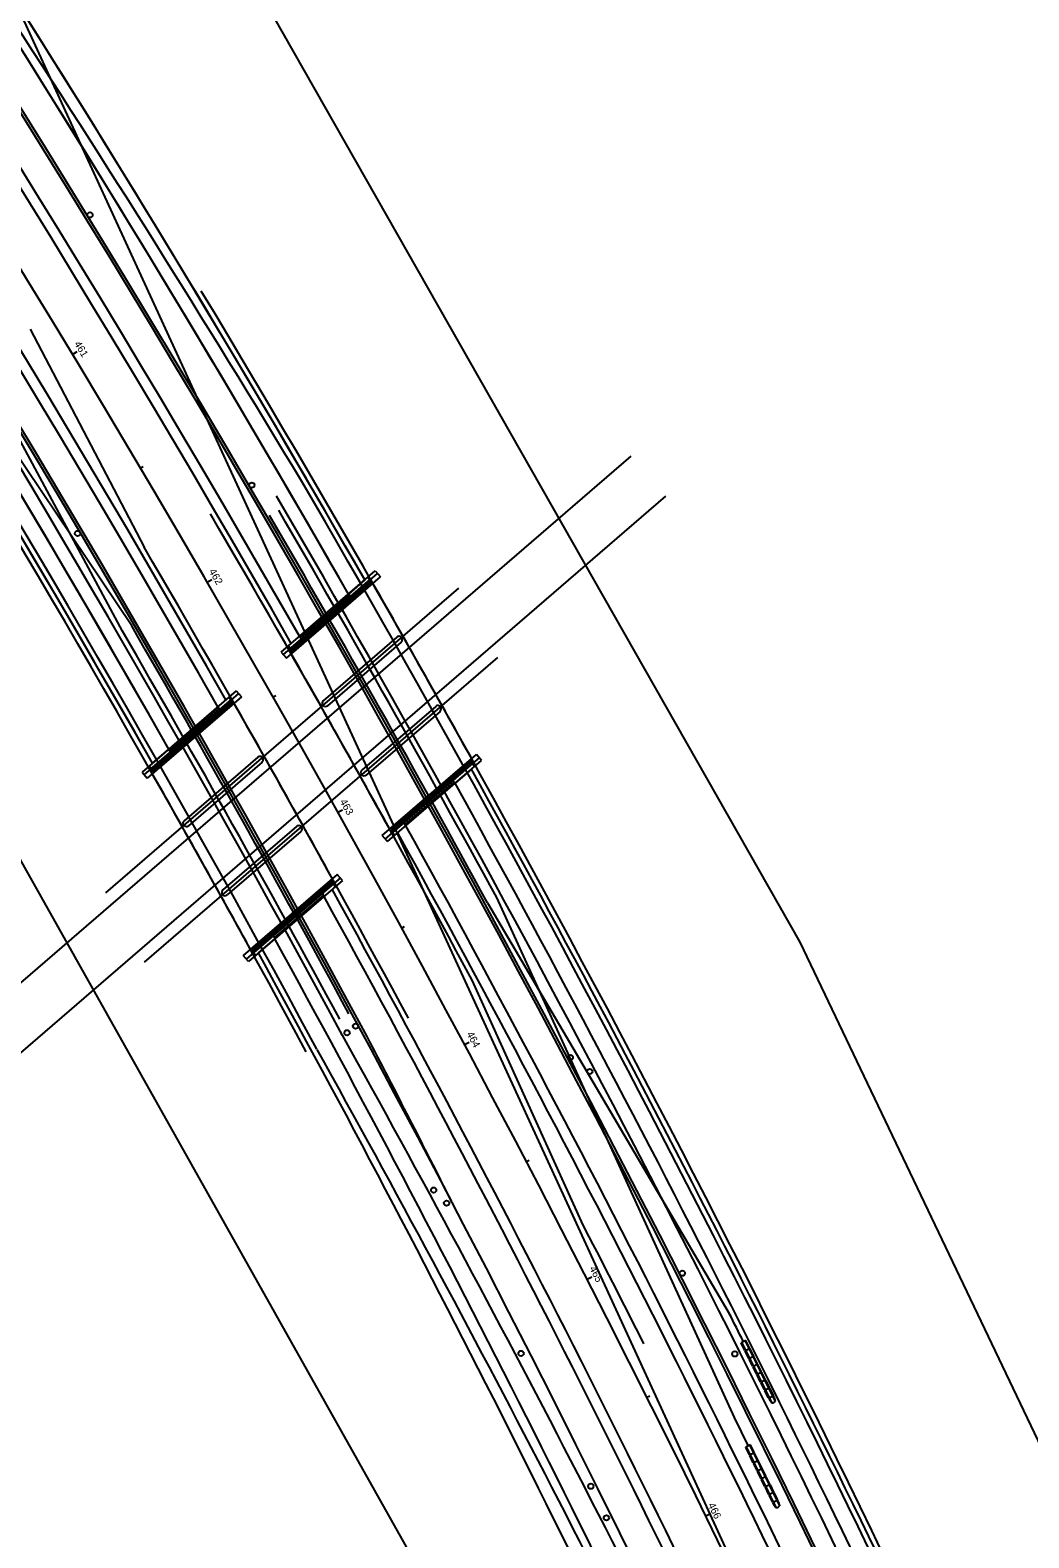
# Model space of a CAD drawing. Extents: x 7786 to 17579, y 337 to 8611.
# Drawn here: x 11436 to 11813, y 4573 to 5143 of the extents above; entities that cross this region are included whole.
import ezdxf

# ---------------------------------------------------------------- set-up
doc = ezdxf.new("R2010")
doc.units = 0
for name, color, linetype in [('BR_P_Slab_Object', 7, 'Continuous'), ('BR_X_Brg_Centerline', 7, 'Continuous'), ('BR_X_Sub_Backwall', 7, 'Continuous'), ('GE_P_Alignment', 7, 'Continuous'), ('GE_P_Alignment_100_Stations', 7, 'Continuous'), ('HY_X_Water_Edge', 7, 'Continuous'), ('MT_P_Edge_Line', 7, 'Continuous'), ('MT_P_PCB', 7, 'Continuous'), ('MT_P_Text', 7, 'Continuous'), ('PM_X_Lane_Line', 7, 'Continuous'), ('PV_P_EOP', 7, 'Continuous'), ('PV_P_Shoulder', 7, 'Continuous'), ('PV_X_EOP', 7, 'Continuous'), ('PV_X_Shoulder', 7, 'Continuous'), ('RD_X_GR_Lt', 7, 'Continuous'), ('RD_X_GR_Rt', 7, 'Continuous'), ('RW_X_Esmt_LA', 7, 'Continuous')]:
    doc.layers.add(name, color=color, linetype=linetype)

msp = doc.modelspace()

# ---------------------------------------------------------------- linework, layer by layer
at = {"layer": 'BR_P_Slab_Object'}
for p, q in [((11533.81, 4908.92), (11564.66, 4935.55)), ((11481.34, 4863.64), (11512.21, 4890.28)), ((11572.76, 4839.57), (11603.7, 4866.27)), ((11520.14, 4794.16), (11551.1, 4820.88))]:
    msp.add_line(p, q, dxfattribs=at)
for radius, start, end in [(5783.58, 29.009315, 29.797103), (5743.58, 28.92605, 29.71955), (5715.58, 28.86706, 29.6646), (5675.58, 28.78175, 29.58515)]:
    msp.add_arc((6545.73, 2061.51), radius, start, end, dxfattribs=at)
at = {"layer": 'BR_X_Brg_Centerline'}
for p, q in [((11597.93, 4932.19), (11464.49, 4817.03)), ((11612.6, 4906.02), (11479.17, 4790.87))]:
    msp.add_line(p, q, dxfattribs=at)
at = {"layer": 'BR_X_Sub_Backwall'}
for p, q in [((11530.89, 4908.05), (11566.43, 4938.73)), ((11532.85, 4905.78), (11568.39, 4936.46)), ((11534.23, 4909.28), (11564.36, 4935.29)), ((11534.54, 4908.73), (11564.67, 4934.73)), ((11534.85, 4908.17), (11564.98, 4934.17)), ((11563.73, 4936.4), (11564.98, 4934.17)), ((11564.36, 4935.29), (11567.25, 4937.78)), ((11566.43, 4938.73), (11568.39, 4936.46)), ((11538.09, 4913.61), (11556.63, 4929.61)), ((11556.38, 4930.05), (11557, 4928.94)), ((11537.84, 4914.05), (11538.46, 4912.94)), ((11574.59, 4913.7), (11546.77, 4889.69)), ((11576.23, 4911.81), (11548.4, 4887.8)), ((11530.89, 4908.05), (11532.85, 4905.78)), ((11531.71, 4907.11), (11534.23, 4909.28)), ((11533.6, 4910.4), (11534.85, 4908.17)), ((11513.89, 4893.39), (11478.35, 4862.71)), ((11515.85, 4891.12), (11480.31, 4860.44)), ((11511.81, 4889.94), (11481.68, 4863.94)), ((11512.13, 4889.38), (11481.99, 4863.38)), ((11512.44, 4888.83), (11482.31, 4862.82)), ((11511.19, 4891.05), (11512.44, 4888.83)), ((11514.71, 4892.44), (11511.81, 4889.94)), ((11513.89, 4893.39), (11515.85, 4891.12)), ((11507.19, 4886.94), (11488.65, 4870.94)), ((11506.94, 4887.39), (11507.57, 4886.28)), ((11589.27, 4887.54), (11561.45, 4863.53)), ((11590.91, 4885.65), (11563.08, 4861.64)), ((11488.4, 4871.39), (11489.03, 4870.28)), ((11522.03, 4868.34), (11494.21, 4844.33)), ((11523.66, 4866.45), (11495.84, 4842.44)), ((11569.1, 4838.72), (11604.64, 4869.39)), ((11571.06, 4836.45), (11606.6, 4867.12)), ((11572.52, 4841.01), (11602.65, 4867.01)), ((11572.83, 4840.45), (11602.96, 4866.46)), ((11573.14, 4839.9), (11603.27, 4865.9)), ((11603.9, 4864.79), (11602.65, 4867.01)), ((11603.27, 4865.9), (11605.78, 4868.07)), ((11606.6, 4867.12), (11604.64, 4869.39)), ((11478.35, 4862.71), (11480.31, 4860.44)), ((11481.68, 4863.94), (11479.17, 4861.77)), ((11481.06, 4865.05), (11482.31, 4862.82)), ((11577.76, 4842.89), (11596.3, 4858.89)), ((11596.55, 4858.45), (11595.93, 4859.56)), ((11578.01, 4842.45), (11577.39, 4843.56)), ((11536.71, 4842.18), (11508.89, 4818.17)), ((11538.34, 4840.28), (11510.52, 4816.27)), ((11571.06, 4836.45), (11569.1, 4838.72)), ((11570.24, 4837.4), (11573.14, 4839.9)), ((11573.76, 4838.78), (11572.52, 4841.01)), ((11552.1, 4824.05), (11516.56, 4793.38)), ((11554.06, 4821.78), (11518.52, 4791.11)), ((11550.1, 4821.67), (11519.97, 4795.66)), ((11550.42, 4821.11), (11520.28, 4795.11)), ((11550.73, 4820.55), (11520.6, 4794.55)), ((11551.35, 4819.44), (11550.1, 4821.67)), ((11553.25, 4822.73), (11550.73, 4820.55)), ((11554.06, 4821.78), (11552.1, 4824.05)), ((11546.86, 4816.23), (11528.32, 4800.23)), ((11547.11, 4815.78), (11546.49, 4816.9)), ((11528.57, 4799.78), (11527.95, 4800.9)), ((11518.52, 4791.11), (11516.56, 4793.38)), ((11520.6, 4794.55), (11517.71, 4792.06)), ((11521.22, 4793.44), (11519.97, 4795.66))]:
    msp.add_line(p, q, dxfattribs=at)
for centre, radius, start, end in [((6545.73, 2061.51), 5783.58, 29.009315, 29.797103), ((11575.41, 4912.76), 1.25, 310.7944, 130.7944), ((6545.73, 2061.51), 5743.58, 28.92605, 29.71955), ((6545.73, 2061.51), 5715.58, 28.86706, 29.6646), ((11547.59, 4888.75), 1.25, 130.7944, 310.7944), ((11590.09, 4886.59), 1.25, 310.7944, 130.7944), ((11522.85, 4867.39), 1.25, 310.7944, 130.7944), ((6545.73, 2061.51), 5675.58, 28.78175, 29.58515), ((11562.27, 4862.58), 1.25, 130.7944, 310.7944), ((11495.03, 4843.38), 1.25, 130.7944, 310.7944), ((11537.53, 4841.23), 1.25, 310.7944, 130.7944), ((11509.7, 4817.22), 1.25, 130.7944, 310.7944)]:
    msp.add_arc(centre, radius, start, end, dxfattribs=at)
at = {"layer": 'GE_P_Alignment'}
msp.add_line((11244.05, 5559.32), (12302.66, 3255.22), dxfattribs=at)
msp.add_arc((6545.73, 2061.51), 5729.58, 24.676389, 48.6575, dxfattribs=at)
msp.add_arc((6545.73, 2061.51), 5729.58, 24.676389, 48.6575, dxfattribs=at)
at = {"layer": 'GE_P_Alignment_100_Stations'}
for p, q in [((11452.06, 5020.55), (11453.78, 5021.59)), ((11477.7, 4977.63), (11478.73, 4978.24)), ((11477.7, 4977.63), (11478.73, 4978.24)), ((11502.96, 4934.48), (11504.69, 4935.48)), ((11527.84, 4891.11), (11528.89, 4891.7)), ((11527.84, 4891.11), (11528.89, 4891.7)), ((11552.35, 4847.52), (11554.09, 4848.49)), ((11576.47, 4803.73), (11577.52, 4804.3)), ((11576.47, 4803.73), (11577.52, 4804.3)), ((11600.21, 4759.72), (11601.97, 4760.66)), ((11623.56, 4715.51), (11624.62, 4716.07)), ((11623.56, 4715.51), (11624.62, 4716.07)), ((11646.53, 4671.1), (11648.31, 4672.01)), ((11669.1, 4626.49), (11670.18, 4627.02)), ((11669.1, 4626.49), (11670.18, 4627.02)), ((11691.29, 4581.68), (11693.09, 4582.56))]:
    msp.add_line(p, q, dxfattribs=at)
at = {"layer": 'HY_X_Water_Edge'}
for p, q in [((11662.98, 4982.09), (11408.68, 4762.63)), ((11676.05, 4966.95), (11421.75, 4747.49))]:
    msp.add_line(p, q, dxfattribs=at)
at = {"layer": 'MT_P_Edge_Line'}
for centre in [(11458.66, 5073.23), (11519.8, 4971.14), (11453.96, 4952.92), (11559, 4766.71), (11640.15, 4754.86), (11593.41, 4699.79), (11682.44, 4673.31), (11647.89, 4592.83)]:
    msp.add_circle(centre, 1, dxfattribs=at)
for centre, radius, start, end in [((6545.73, 2061.51), 5698.58, 28.29546, 48.6575), ((6545.73, 2061.51), 5760.58, 24.676389, 34.594405), ((6508.39, 2134.21), 5697.58, 26.77261, 27.47379)]:
    msp.add_arc(centre, radius, start, end, dxfattribs=at)
at = {"layer": 'MT_P_PCB'}
for p, q in [((11474.41, 4917.93), (11374.11, 5067.39)), ((11608.85, 4813.25), (11700.2, 4658.15)), ((11706.48, 4647.88), (11704.69, 4646.98)), ((11706.1, 4644.15), (11704.69, 4646.98)), ((11716.36, 4624.32), (11704.99, 4647.13)), ((11706.1, 4644.15), (11706.33, 4644.07)), ((11706.18, 4647.73), (11717.55, 4624.92)), ((11706.33, 4644.07), (11706.25, 4643.85)), ((11707.59, 4641.17), (11706.25, 4643.85)), ((11707.82, 4644.82), (11706.33, 4644.07)), ((11707.89, 4645.04), (11706.48, 4647.88)), ((11707.89, 4645.04), (11707.82, 4644.82)), ((11707.82, 4644.82), (11708.04, 4644.74)), ((11709.38, 4642.06), (11708.04, 4644.74)), ((11707.59, 4641.17), (11707.81, 4641.09)), ((11707.81, 4641.09), (11707.74, 4640.87)), ((11709.08, 4638.18), (11707.74, 4640.87)), ((11709.31, 4641.83), (11707.81, 4641.09)), ((11709.08, 4638.18), (11709.3, 4638.11)), ((11709.3, 4638.11), (11709.23, 4637.88)), ((11710.56, 4635.2), (11709.23, 4637.88)), ((11710.79, 4638.85), (11709.3, 4638.11)), ((11709.38, 4642.06), (11709.31, 4641.83)), ((11709.31, 4641.83), (11709.53, 4641.76)), ((11710.87, 4639.08), (11709.53, 4641.76)), ((11710.87, 4639.08), (11710.79, 4638.85)), ((11710.79, 4638.85), (11711.02, 4638.78)), ((11712.35, 4636.09), (11711.02, 4638.78)), ((11710.56, 4635.2), (11710.79, 4635.12)), ((11710.79, 4635.12), (11710.71, 4634.9)), ((11712.05, 4632.22), (11710.71, 4634.9)), ((11712.28, 4635.87), (11710.79, 4635.12)), ((11712.05, 4632.22), (11712.28, 4632.14)), ((11712.28, 4632.14), (11712.2, 4631.92)), ((11713.54, 4629.23), (11712.2, 4631.92)), ((11712.35, 4636.09), (11712.28, 4635.87)), ((11712.28, 4635.87), (11712.5, 4635.79)), ((11713.77, 4632.88), (11712.28, 4632.14)), ((11713.84, 4633.11), (11712.5, 4635.79)), ((11713.84, 4633.11), (11713.77, 4632.88)), ((11713.77, 4632.88), (11713.99, 4632.81)), ((11713.99, 4632.81), (11715.33, 4630.13)), ((11713.54, 4629.23), (11713.76, 4629.16)), ((11713.76, 4629.16), (11713.69, 4628.93)), ((11715.03, 4626.25), (11713.69, 4628.93)), ((11715.25, 4629.9), (11713.76, 4629.16)), ((11715.03, 4626.25), (11715.25, 4626.17)), ((11715.33, 4630.13), (11715.25, 4629.9)), ((11715.25, 4629.9), (11715.48, 4629.83)), ((11716.74, 4626.92), (11715.25, 4626.17)), ((11715.48, 4629.83), (11716.82, 4627.14)), ((11716.82, 4627.14), (11716.74, 4626.92)), ((11716.74, 4626.92), (11716.96, 4626.84)), ((11716.96, 4626.84), (11717.16, 4626.45)), ((11717.16, 4626.45), (11717.6, 4625)), ((11715.25, 4626.17), (11715.17, 4625.95)), ((11715.37, 4625.56), (11715.17, 4625.95)), ((11715.37, 4625.56), (11716.26, 4624.33))]:
    msp.add_line(p, q, dxfattribs=at)
for centre, radius, start, end in [((6545.73, 2061.51), 5762.58, 28.523456, 30.193834), ((6545.73, 2061.51), 5696.58, 28.40467, 30.09441), ((6546.25, 2060.48), 5771.58, 26.629719, 26.748846), ((11716.44, 4625.65), 1.34, 262.3156, 330.667)]:
    msp.add_arc(centre, radius, start, end, dxfattribs=at)
at = {"layer": 'MT_P_Text'}
for p, q in [((11470.95, 4915.92), (11368.68, 5106.18)), ((11612.31, 4815.26), (11702, 4618.76)), ((11702, 4618.76), (11707.32, 4608.01)), ((11708.22, 4608.45), (11706.42, 4607.57)), ((11707.82, 4604.72), (11706.42, 4607.57)), ((11717.95, 4584.83), (11706.72, 4607.71)), ((11707.82, 4604.72), (11708.04, 4604.65)), ((11707.92, 4608.3), (11719.15, 4585.42)), ((11708.04, 4604.65), (11707.96, 4604.43)), ((11709.29, 4601.73), (11707.96, 4604.43)), ((11709.54, 4605.38), (11708.04, 4604.65)), ((11709.61, 4605.61), (11708.22, 4608.45)), ((11709.61, 4605.61), (11709.54, 4605.38)), ((11709.54, 4605.38), (11709.76, 4605.31)), ((11711.08, 4602.61), (11709.76, 4605.31)), ((11709.29, 4601.73), (11709.51, 4601.66)), ((11709.51, 4601.66), (11709.43, 4601.43)), ((11710.75, 4598.74), (11709.43, 4601.43)), ((11711, 4602.39), (11709.51, 4601.66)), ((11710.75, 4598.74), (11710.98, 4598.66)), ((11710.98, 4598.66), (11710.9, 4598.44)), ((11712.22, 4595.75), (11710.9, 4598.44)), ((11712.47, 4599.4), (11710.98, 4598.66)), ((11711.08, 4602.61), (11711, 4602.39)), ((11711, 4602.39), (11711.23, 4602.31)), ((11712.55, 4599.62), (11711.23, 4602.31)), ((11712.55, 4599.62), (11712.47, 4599.4)), ((11712.47, 4599.4), (11712.7, 4599.32)), ((11714.02, 4596.63), (11712.7, 4599.32)), ((11712.22, 4595.75), (11712.44, 4595.67)), ((11712.44, 4595.67), (11712.37, 4595.45)), ((11713.69, 4592.75), (11712.37, 4595.45)), ((11713.94, 4596.4), (11712.44, 4595.67)), ((11713.69, 4592.75), (11713.91, 4592.68)), ((11713.91, 4592.68), (11713.84, 4592.46)), ((11715.16, 4589.76), (11713.84, 4592.46)), ((11715.41, 4593.41), (11713.91, 4592.68)), ((11714.02, 4596.63), (11713.94, 4596.4)), ((11713.94, 4596.4), (11714.16, 4596.33)), ((11715.49, 4593.64), (11714.16, 4596.33)), ((11715.49, 4593.64), (11715.41, 4593.41)), ((11715.41, 4593.41), (11715.63, 4593.34)), ((11715.63, 4593.34), (11716.95, 4590.64)), ((11715.16, 4589.76), (11715.38, 4589.69)), ((11715.38, 4589.69), (11715.3, 4589.46)), ((11716.63, 4586.77), (11715.3, 4589.46)), ((11716.88, 4590.42), (11715.38, 4589.69)), ((11716.63, 4586.77), (11716.85, 4586.69)), ((11716.85, 4586.69), (11716.77, 4586.47)), ((11716.96, 4586.08), (11716.77, 4586.47)), ((11718.35, 4587.43), (11716.85, 4586.69)), ((11716.95, 4590.64), (11716.88, 4590.42)), ((11716.88, 4590.42), (11717.1, 4590.34)), ((11717.1, 4590.34), (11718.42, 4587.65)), ((11718.42, 4587.65), (11718.35, 4587.43)), ((11718.35, 4587.43), (11718.57, 4587.35)), ((11718.57, 4587.35), (11718.76, 4586.96)), ((11718.76, 4586.96), (11719.2, 4585.5)), ((11716.96, 4586.08), (11717.85, 4584.84))]:
    msp.add_line(p, q, dxfattribs=at)
for centre in [(11555.8, 4764.21), (11647.47, 4749.57), (11588.51, 4704.77), (11621.52, 4643.04), (11702.3, 4642.84), (11653.77, 4580.9)]:
    msp.add_circle(centre, 1, dxfattribs=at)
for centre, radius, start, end in [((6545.73, 2061.51), 5690.58, 28.34441, 35.6444), ((6545.73, 2061.51), 5679.58, 28.34441, 35.6444), ((6592.52, 1994.31), 5773.58, 31.053521, 35.256126), ((6545.73, 2061.51), 5779.58, 24.676389, 30.243401), ((6545.73, 2061.51), 5768.58, 24.676389, 30.243496), ((6545.73, 2061.51), 5766.58, 28.524609, 30.193834), ((6545.73, 2061.51), 5692.58, 28.40349, 30.09441), ((6578.82, 1986.65), 5697.58, 25.49702, 29.16504), ((6578.85, 1986.6), 5686.58, 25.49763, 29.16565), ((11718.04, 4586.16), 1.34, 261.9562, 330.3076)]:
    msp.add_arc(centre, radius, start, end, dxfattribs=at)
at = {"layer": 'PM_X_Lane_Line'}
for radius, start in [(5761.58, 24.676389), (5697.58, 24.67639)]:
    msp.add_arc((6545.73, 2061.51), radius, start, 48.6575, dxfattribs=at)
at = {"layer": 'PV_P_EOP'}
for radius, start, end in [(5685.58, 29.60201, 47.0944), (5773.58, 29.790455, 34.494405), (5773.58, 24.676389, 28.975937), (5685.58, 24.67639, 28.79031)]:
    msp.add_arc((6545.73, 2061.51), radius, start, end, dxfattribs=at)
at = {"layer": 'PV_P_Shoulder'}
for p, q in [((11562.49, 4935.32), (11556.32, 4930)), ((11482.25, 4866.08), (11488.43, 4871.41)), ((11602.77, 4863.82), (11596.59, 4858.48)), ((11522.31, 4794.38), (11528.5, 4799.72))]:
    msp.add_line(p, q, dxfattribs=at)
for radius, start, end in [(5677.58, 29.60201, 47.0944), (5781.58, 29.805871, 34.494405), (5781.58, 24.676389, 28.992525), (5677.58, 24.67639, 28.77314)]:
    msp.add_arc((6545.73, 2061.51), radius, start, end, dxfattribs=at)
at = {"layer": 'PV_X_EOP'}
for radius, start, end in [(5773.58, 29.790455, 48.6575), (5749.58, 29.743945, 48.6575), (5709.58, 29.66554, 48.6575), (5685.58, 29.61796, 48.6575), (5773.58, 24.676389, 28.975937), (5749.58, 24.676389, 28.925887), (5709.58, 24.67639, 28.84152), (5685.58, 24.67639, 28.79031)]:
    msp.add_arc((6545.73, 2061.51), radius, start, end, dxfattribs=at)
at = {"layer": 'PV_X_Shoulder'}
for radius, start, end in [(5781.58, 29.805871, 48.6575), (5745.58, 29.736155, 48.6575), (5713.58, 29.67343, 48.6575), (5677.58, 29.60201, 48.6575), (5781.58, 24.676389, 28.992525), (5745.58, 24.676389, 28.917504), (5713.58, 24.67639, 28.85001), (5677.58, 24.67639, 28.77314)]:
    msp.add_arc((6545.73, 2061.51), radius, start, end, dxfattribs=at)
at = {"layer": 'RD_X_GR_Lt'}
for p, q in [((11436.05, 5030.12), (11479.07, 4947.68)), ((11644.31, 4692.92), (11603.06, 4784.02))]:
    msp.add_line(p, q, dxfattribs=at)
for radius, start, end in [(5743.58, 28.294817, 30.310844), (5715.58, 28.28285, 30.32897), (5737.58, 26.779242, 27.298519)]:
    msp.add_arc((6545.73, 2061.51), radius, start, end, dxfattribs=at)
at = {"layer": 'RD_X_GR_Rt'}
for radius, start, end in [(5675.58, 28.35494, 34.69774), (5783.58, 24.676389, 31.04807)]:
    msp.add_arc((6545.73, 2061.51), radius, start, end, dxfattribs=at)
at = {"layer": 'RW_X_Esmt_LA'}
for points in [[(11225.16, 5599.82), (11461.42, 5265.33), (11726.86, 4798.39), (12014, 4197.07)], [(11037.71, 5458.09), (11309.03, 5048.88), (11665.76, 4413.91), (11802.46, 4096.06)]]:
    msp.add_lwpolyline(points, dxfattribs=at)

# ---------------------------------------------------------------- texts
at = {"layer": 'GE_P_Alignment_100_Stations'}
for s, rotation, p in [('461', 301.0944, (11452.58, 5024.54)), ('462', 300.0944, (11503.48, 4938.57)), ('463', 299.0944, (11552.94, 4851.6)), ('464', 298.0944, (11600.87, 4763.78)), ('465', 297.0944, (11647.25, 4675.18)), ('466', 296.0944, (11692.06, 4585.79))]:
    msp.add_text(s, height=2.8, rotation=rotation, dxfattribs=at).set_placement(p)

doc.saveas('drawing.dxf')
